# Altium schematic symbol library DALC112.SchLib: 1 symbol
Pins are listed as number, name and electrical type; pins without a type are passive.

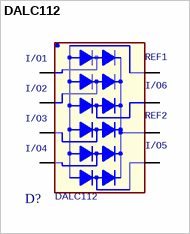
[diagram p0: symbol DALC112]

## DALC112
designator D?
footprint ST_SO8
pins: 1 I/O1, 2 I/O2, 3 I/O3, 4 I/O4, 5 I/O5, 6 REF2, 7 I/O6, 8 REF1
